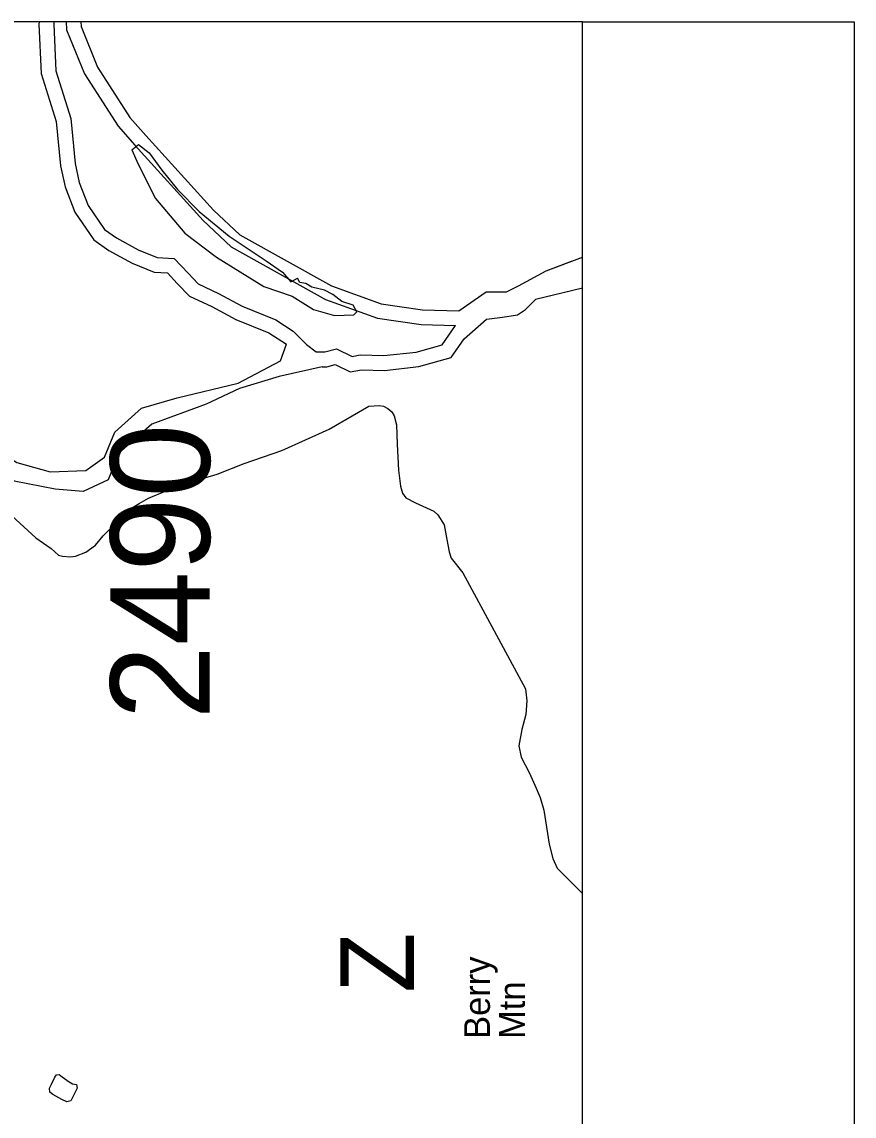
# Model space of a CAD drawing. Extents: x 1373043 to 1375788, y 550128 to 553055.
# Drawn here: x 1373506.3 to 1373623.1, y 550759.4 to 550913 of the extents above; entities that cross this region are included whole.
import ezdxf

# ---------------------------------------------------------------- set-up
doc = ezdxf.new("R2010")
doc.units = 0
for name, color, linetype in [('Old_Level_12', 7, 'Continuous'), ('Old_Level_13', 7, 'Continuous'), ('Old_Level_32', 7, 'Continuous'), ('Old_Level_58', 7, 'Continuous'), ('Old_Level_60', 7, 'Continuous'), ('Old_Level_61', 7, 'Continuous'), ('Old_Level_62', 7, 'Continuous'), ('Prop Dimension Text', 7, 'Continuous')]:
    doc.layers.add(name, color=color, linetype=linetype)

msp = doc.modelspace()

# ---------------------------------------------------------------- linework, layer by layer
at = {"layer": 'Old_Level_13'}
msp.add_line((1373568.38, 550770.28), (1373568.38, 550770.28), dxfattribs=at)
at = {"layer": 'Old_Level_32'}
msp.add_lwpolyline([(1373503.78, 550844.74), (1373508.3, 550840.61), (1373510.44, 550839.11), (1373511.45, 550838.18), (1373512, 550838.03), (1373513.09, 550837.95), (1373513.84, 550838.03), (1373515.31, 550838.6), (1373516.65, 550839.61), (1373517.73, 550840.88), (1373518.87, 550842.02), (1373520.77, 550843.97), (1373521.62, 550844.75), (1373522.76, 550845.44), (1373524.09, 550846.17), (1373526.55, 550847.2), (1373529.78, 550848.4), (1373533.71, 550849.57), (1373537.5, 550851.04), (1373542.81, 550852.89), (1373549.45, 550855.87), (1373552.67, 550857.73), (1373555, 550859.1), (1373556.47, 550859.2), (1373557.08, 550859.1), (1373557.65, 550858.76), (1373558.22, 550858.32), (1373558.55, 550857.73), (1373558.88, 550856.46), (1373558.98, 550853.75), (1373559.17, 550850.13), (1373559.45, 550847.88), (1373559.74, 550846.9), (1373560.21, 550846.22), (1373561.54, 550845.54), (1373564.14, 550844.38), (1373564.7, 550843.86), (1373565.56, 550842.46), (1373565.93, 550840.36), (1373566.28, 550838.64), (1373566.56, 550837.76), (1373568.19, 550835.72), (1373577, 550819.4), (1373577.18, 550817.73), (1373577.05, 550815.8), (1373576.46, 550813.7), (1373576.04, 550811.44), (1373576.38, 550809.85), (1373577.56, 550807.6), (1373578.48, 550805.49), (1373579.06, 550804.15), (1373579.57, 550802.39), (1373580.32, 550797.61), (1373580.82, 550795.6), (1373581.41, 550794.26), (1373584.98, 550790.69)], dxfattribs=at)
at = {"layer": 'Old_Level_58'}
for points in [[(1373508.74, 550913.04), (1373508.71, 550912.74), (1373509.03, 550905.79), (1373511.14, 550899.05), (1373511.76, 550892.86), (1373512.4, 550889.91), (1373513.77, 550886.33), (1373516.4, 550882.43), (1373518.51, 550880.95), (1373521.78, 550879.16), (1373524.87, 550877.92), (1373526.76, 550877.81), (1373528.13, 550876.34), (1373529.82, 550874.55), (1373532.98, 550873.07), (1373536.36, 550871.28), (1373540.99, 550869.38), (1373543.44, 550867.8)], [(1373508.74, 550913.04), (1373508.71, 550912.74), (1373509.03, 550905.79), (1373511.14, 550899.05), (1373511.76, 550892.86), (1373512.4, 550889.91), (1373513.77, 550886.33), (1373516.4, 550882.43), (1373518.51, 550880.95), (1373521.78, 550879.16), (1373524.87, 550877.92), (1373526.76, 550877.81), (1373528.13, 550876.34), (1373529.82, 550874.55), (1373532.98, 550873.07), (1373536.36, 550871.28), (1373540.99, 550869.38), (1373543.44, 550867.8)], [(1373514.61, 550913.04), (1373514.63, 550912.38), (1373516.95, 550906.69), (1373521.48, 550899.64), (1373523.7, 550897.11), (1373533.23, 550886.61), (1373536.92, 550883.13), (1373549.78, 550875.97), (1373556.73, 550873.45), (1373562.52, 550872.62), (1373567.63, 550872.49)], [(1373514.61, 550913.04), (1373514.63, 550912.38), (1373516.95, 550906.69), (1373521.48, 550899.64), (1373523.7, 550897.11), (1373533.23, 550886.61), (1373536.92, 550883.13), (1373549.78, 550875.97), (1373556.73, 550873.45), (1373562.52, 550872.62), (1373567.63, 550872.49)], [(1373567.63, 550872.49), (1373571.47, 550875.15), (1373574.32, 550875.15), (1373576, 550875.99), (1373579.9, 550878.1), (1373584.98, 550880.01)], [(1373567.63, 550872.49), (1373571.47, 550875.15), (1373574.32, 550875.15), (1373576, 550875.99), (1373579.9, 550878.1), (1373583.46, 550879.44)], [(1373584.98, 550875.68), (1373578.4, 550874.08)], [(1373583.46, 550875.31), (1373578.4, 550874.08)], [(1373548.44, 550864.64), (1373549.11, 550864.64), (1373550.27, 550864.96), (1373552.38, 550863.91), (1373553.96, 550864.22), (1373557.19, 550864.13), (1373562.04, 550864.65), (1373566.58, 550865.92), (1373568.37, 550868.55), (1373571.53, 550871.29), (1373573.74, 550871.61), (1373575.85, 550871.92), (1373576.99, 550872.66), (1373578.4, 550874.08)], [(1373548.44, 550864.64), (1373549.11, 550864.64), (1373550.27, 550864.96), (1373552.38, 550863.91), (1373553.96, 550864.22), (1373557.19, 550864.13), (1373562.04, 550864.65), (1373566.58, 550865.92), (1373568.37, 550868.55), (1373571.53, 550871.29), (1373573.74, 550871.61), (1373575.85, 550871.92), (1373576.99, 550872.66), (1373578.4, 550874.08)]]:
    msp.add_lwpolyline(points, dxfattribs=at)
at = {"layer": 'Old_Level_60'}
for points in [[(1373521.73, 550895.09), (1373522.68, 550895.83), (1373524.16, 550894.67), (1373525.95, 550892.25), (1373528.16, 550889.51), (1373531.19, 550886.45), (1373535.41, 550882.98), (1373540.58, 550879.5), (1373542.89, 550877.92), (1373544.05, 550876.55), (1373545, 550877.08)], [(1373521.73, 550895.09), (1373522.65, 550893.09), (1373525.08, 550888.24), (1373529.19, 550883.4), (1373533.62, 550880.03), (1373540.26, 550875.92), (1373544.26, 550874.55), (1373547.22, 550872.65), (1373550.17, 550871.81), (1373552.91, 550871.92), (1373553.33, 550872.34), (1373552.8, 550873.29), (1373551.22, 550873.81), (1373549.96, 550874.76), (1373548.8, 550875.39), (1373547.01, 550875.81), (1373546.16, 550876.34), (1373545.32, 550876.45), (1373545, 550877.08)], [(1373460.84, 550848.59), (1373463.82, 550851.74), (1373469.21, 550851.93), (1373470.88, 550854.34), (1373479.24, 550852.86), (1373485.93, 550854.9), (1373495.22, 550857.31), (1373498.73, 550856.81), (1373502.4, 550853.3), (1373505.62, 550851.19), (1373510.27, 550849.89), (1373515.28, 550850.07), (1373517.89, 550851.93), (1373519.37, 550855.46), (1373523.09, 550858.8), (1373528.1, 550860.28), (1373536.65, 550862.33), (1373542.6, 550865.48), (1373543.44, 550867.8)], [(1373548.44, 550864.64), (1373542.41, 550863.25), (1373536.84, 550861.58), (1373532.19, 550859.36), (1373524.57, 550856.57), (1373519.93, 550852.49), (1373518.44, 550848.77), (1373514.91, 550847.1), (1373511.01, 550847.47), (1373505.25, 550848.59), (1373502.09, 550851), (1373500.05, 550854.34), (1373497.15, 550855.45), (1373492.53, 550853.93), (1373488.16, 550852.86), (1373483.88, 550851.56), (1373477.2, 550851.19), (1373470.51, 550852.3), (1373463.82, 550850.44), (1373461.4, 550848.21)]]:
    msp.add_lwpolyline(points, dxfattribs=at)
at = {"layer": 'Old_Level_61'}
for points in [[(1373510.81, 550913.04), (1373510.78, 550912.7), (1373511.08, 550906.15), (1373513.17, 550899.46), (1373513.81, 550893.18), (1373514.38, 550890.5), (1373515.61, 550887.29), (1373517.9, 550883.9), (1373519.6, 550882.71), (1373522.66, 550881.04), (1373525.32, 550879.96), (1373527.71, 550879.83), (1373529.64, 550877.75), (1373531.05, 550876.25), (1373533.9, 550874.92), (1373537.23, 550873.15), (1373541.96, 550871.22), (1373544.41, 550869.63), (1373546.27, 550867.77), (1373547.61, 550866.71), (1373548.83, 550866.71), (1373550.49, 550867.16), (1373552.67, 550866.07), (1373553.79, 550866.3), (1373557.11, 550866.2), (1373561.65, 550866.69), (1373565.29, 550867.71), (1373567.15, 550870.43)], [(1373512.55, 550913.04), (1373512.58, 550911.95), (1373515.11, 550905.74), (1373519.83, 550898.39), (1373522.15, 550895.73), (1373531.76, 550885.16), (1373535.69, 550881.45), (1373548.92, 550874.08), (1373556.23, 550871.43), (1373562.35, 550870.56), (1373567.15, 550870.43)]]:
    msp.add_lwpolyline(points, dxfattribs=at)
at = {"layer": 'Old_Level_62'}
msp.add_lwpolyline([(1373510.48, 550763.93), (1373510.93, 550764.93), (1373511.17, 550765.24), (1373511.56, 550765.29), (1373511.99, 550764.97), (1373512.94, 550764.25), (1373513.42, 550763.99), (1373513.99, 550763.86), (1373514.06, 550763.35), (1373513.65, 550762.54), (1373513.19, 550761.6), (1373512.62, 550761.43), (1373511.93, 550761.75), (1373510.68, 550762.48), (1373510.24, 550762.8), (1373510.21, 550763.37), (1373510.48, 550763.93)], dxfattribs=at)
at = {"layer": 'Prop Dimension Text'}
for points in [[(1373088.48, 550913.04), (1373088.48, 550416.54), (1373584.98, 550416.54), (1373584.98, 550913.04)], [(1373623.1, 550913.04), (1373623.1, 550416.54), (1373584.98, 550416.54), (1373584.98, 550913.04)]]:
    msp.add_lwpolyline(points, close=True, dxfattribs=at)

# ---------------------------------------------------------------- texts
at = {"layer": 'Old_Level_12'}
msp.add_text('2490', height=13.952, rotation=90, dxfattribs=at).set_placement((1373532.69, 550815.13))
at = {"layer": 'Old_Level_13'}
for s, height, p in [('Z', 10.33, (1373561.34, 550776.77)), ('Berry', 3.617, (1373572, 550770.28)), ('Mtn', 3.617, (1373576.9, 550770.28))]:
    msp.add_text(s, height=height, rotation=90, dxfattribs=at).set_placement(p)

doc.saveas('drawing.dxf')
